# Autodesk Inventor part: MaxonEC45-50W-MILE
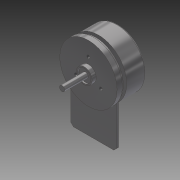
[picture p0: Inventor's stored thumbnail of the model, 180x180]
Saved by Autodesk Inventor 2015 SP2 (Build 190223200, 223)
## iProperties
Created: 2015-08
Part Number: MaxonEC45-50W-MILE
Material: Edelstahl
Document SubType Name: Modeling
Designer: ryll
Mass: 265.019 g
Surface Area: 72.2075 cm^2
Volume: 33.1274 cm^3
Density: 8 g/cm^3
Appearance: Halbpoliert
Author: ryll
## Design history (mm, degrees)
sketch "Skizze1"
  geometry: L1 (0, 26.4)-(0, -4.4) reference; L2 (0, 6)-(0, 22); L3 (0, 22)-(4, 22); L4 (4, 22)-(4, 21.2); L5 (4, 21.2)-(5.6, 21.2); L6 (5.6, 21.2)-(5.6, 18.25); L7 (5.6, 18.25)-(7.7, 18.25); L8 (7.7, 18.25)-(7.7, 21.7); L9 (7.7, 21.7)-(22.6, 21.7); L10 (22.6, 21.7)-(22.6, 0); L11 (-20.2, 0)-(22.6, 0); L12 (0, 6)-(-3.2, 6); L13 (-3.2, 6)-(-3.2, 2); L14 (-3.2, 2)-(-20.2, 2); L15 (-20.2, 2)-(-20.2, 0); L16 (-28.76, 0)-(31.16, 0) reference; L17 (-20.2, 0)-(22.6, 0); 1 further point
  constraints: 30 end point, 9 perpendicular, 3 collinear, 3 horizontal, 1 vertical
  dimensions: "d0" = 44 diameter of L3 L11; "d1" = 4 distance of L2.end L3.end; "d2" = 1.6 distance of L4.end L5.end; "d3" = 2.1 distance of L6.end L7.end; "d4" = 22.6 distance between parallel lines of L2 L10; "d5" = 43.4 diameter of L9 L11; "d6" = 12 diameter of L12 L11; "d7" = 4 diameter of L14 L11; "d8" = 3.2 distance of L2.start L12.end; "d9" = 20.2 distance between parallel lines of L2 L15; "d10" = 42.4 diameter of L5 L11; "d11" = 36.5 diameter of L7 L11
revolve "Umdrehung1" sketch "Skizze1" stored, may be unused: angle "d12" = 90 deg
fillet "Rundung1" dims "d13" = 1
sketch "Skizze2"
  geometry: C1 r 6 at (0, 0) reference; C2 r 5 at (0, 0); C3 r 2 at (0, 0); 1 further point
  constraints: 2 centre point, 2 coincident
  dimensions: "d14" = 1 radial gap between concentric circles of C1 C2
extrude "Extrusion1" cut sketch "Skizze2" distance "d15" = 1; taper "d16" = 0 deg
sketch "Skizze3"
  geometry: L1 (0, 30.8)-(0, -30.8) reference; L2 (-30.8, 0)-(30.8, 0) reference; 2 further points
  constraints: 1 point on line
  dimensions: "d17" = 11 distance from line of point (0, 11) L2
hole "Bohrung1" sketch "Skizze3" at (0, 11) diameter "d18" = 2.459; stored, may be unused: countersink angle "d22" = 90 deg, drill point angle "d24" = 118 deg; dims "d19" = 6, "d20" = 4, "d21" = 2, "d23" = 3.9
pattern_circular "Runde Anordnung1" dims angle "d26" = 360 deg
sketch "Skizze4"
  geometry: L1 (30.8, 0)-(-30.8, 0) reference; L2 (-17.5, 11.966)-(-17.5, 45.3); L3 (-17.5, 45.3)-(17.5, 45.3); L4 (17.5, 45.3)-(17.5, 11.966); L5 (0, 52.313)-(0, -34.386) reference; A1 r 21.2 centre (0, 0) between (17.5, 11.966) and (-17.5, 11.966) reference; A2 r 21.2 centre (0, 0) between (17.5, 11.966) and (-17.5, 11.966); 1 further point
  constraints: 6 end point, 4 point on circle, 2 parallel, 1 centre point, 1 concentric, 1 other
  dimensions: "d28" = 35 distance of L2.end L3.end; "d29" = 45.3 distance between parallel lines of L3 L1
extrude "Extrusion2" join sketch "Skizze4" distance "d30" = 1.6; taper "d31" = 0 deg
chamfer "Fase1" distance "d32" = 2; stored, may be unused: second distance "d33" = 2, angle "d34" = 45 deg
node "Volumenkörper1"
